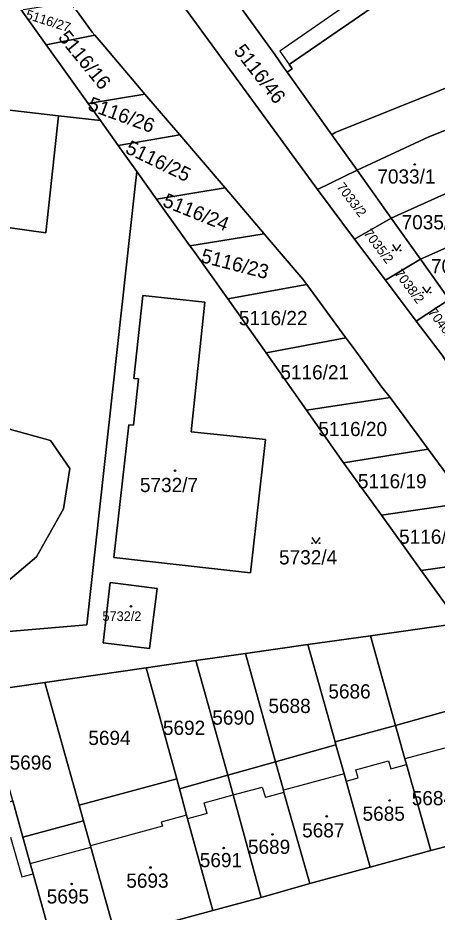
# Model space of a CAD drawing. Extents: x -596233 to -595156, y -1161235 to -1159375.
# Drawn here: x -595296 to -595245.9, y -1160579.1 to -1160472 of the extents above; entities that cross this region are included whole.
import ezdxf

# ---------------------------------------------------------------- set-up
doc = ezdxf.new("R2010")
doc.units = 0
for name, color, linetype in [('KN_CAR_KR', 7, 'Continuous'), ('KN_KULTURY', 7, 'Continuous'), ('KN_PARC_CIS_POZ', 7, 'Continuous'), ('KN_PARC_CIS_STAV', 7, 'Continuous'), ('KN_PARC_PLOCHA', 7, 'Continuous'), ('parcely_l', 7, 'Continuous')]:
    doc.layers.add(name, color=color, linetype=linetype)

msp = doc.modelspace()

# ---------------------------------------------------------------- linework, layer by layer
at = {"layer": 'KN_CAR_KR'}
for points in [[(-595254.62, -1160469.02), (-595264.73, -1160476.04)], [(-595264.73, -1160476.04), (-595263.59, -1160477.64)], [(-595241.88, -1160558.62), (-595249.75, -1160560.73)], [(-595255.63, -1160562.06), (-595251.72, -1160560.99)], [(-595251.72, -1160560.99), (-595251.45, -1160561.96)], [(-595251.45, -1160561.96), (-595249.55, -1160561.44)], [(-595257.03, -1160562.54), (-595264.26, -1160564.51)], [(-595255.36, -1160563.03), (-595255.63, -1160562.06)], [(-595256.79, -1160563.42), (-595255.36, -1160563.03)], [(-595273.78, -1160566.01), (-595270.31, -1160565.07)], [(-595270.31, -1160565.07), (-595266.83, -1160564.14)], [(-595266.83, -1160564.14), (-595266.44, -1160565.39)], [(-595264.23, -1160564.79), (-595266.44, -1160565.39)], [(-595273.42, -1160567.3), (-595273.78, -1160566.01)], [(-595275.86, -1160567.48), (-595278.89, -1160568.31)], [(-595278.89, -1160568.31), (-595278.76, -1160568.8)], [(-595273.42, -1160567.3), (-595275.74, -1160567.93)], [(-595278.76, -1160568.8), (-595287.37, -1160571.16)], [(-595296.91, -1160570.12), (-595295.57, -1160574.88)], [(-595294.57, -1160573.26), (-595287.33, -1160571.32)], [(-595295.57, -1160574.88), (-595294.22, -1160574.5)]]:
    msp.add_lwpolyline(points, dxfattribs=at)
at = {"layer": 'KN_KULTURY'}
for points in [[(-595251.2418, -1160499.1816), (-595250.7418, -1160499.9316), (-595250.2418, -1160499.1816)], [(-595247.6418, -1160504.2316), (-595247.1418, -1160504.9816), (-595246.6418, -1160504.2316)], [(-595260.9018, -1160534.2316), (-595260.4018, -1160534.9816), (-595259.9018, -1160534.2316)]]:
    msp.add_lwpolyline(points, dxfattribs=at)
for centre, radius in [((-595248.58, -1160489.59), 0.09), ((-595248.58, -1160489.59), 0.0398), ((-595251.192, -1160499.8814), 0.05), ((-595250.2926, -1160499.8814), 0.05), ((-595247.592, -1160504.9314), 0.05), ((-595246.6926, -1160504.9314), 0.05), ((-595277.25, -1160526.26), 0.09), ((-595277.25, -1160526.26), 0.0398), ((-595260.852, -1160534.9314), 0.05), ((-595259.9526, -1160534.9314), 0.05), ((-595282.52, -1160542.49), 0.09), ((-595282.52, -1160542.49), 0.0398), ((-595251.59, -1160565.73), 0.09), ((-595251.59, -1160565.73), 0.0398), ((-595259.11, -1160567.64), 0.09), ((-595259.11, -1160567.64), 0.0398), ((-595265.59, -1160569.8), 0.09), ((-595265.59, -1160569.8), 0.0398), ((-595271.44, -1160571.43), 0.09), ((-595271.44, -1160571.43), 0.0398), ((-595280.18, -1160573.76), 0.09), ((-595280.18, -1160573.76), 0.0398), ((-595289.62, -1160575.73), 0.09), ((-595289.62, -1160575.73), 0.0398)]:
    msp.add_circle(centre, radius, dxfattribs=at)
at = {"layer": 'KN_PARC_PLOCHA'}
for points in [[(-595308.89, -1160451.79), (-595304.32, -1160458.48), (-595297.46, -1160468.53), (-595295.64, -1160471.08), (-595292.65, -1160475.27), (-595287.63, -1160482.29), (-595286.17, -1160484.34), (-595291.19, -1160483.77), (-595304.64, -1160482.23), (-595305.5, -1160490.09), (-595324.43, -1160488.01), (-595323.19, -1160476.74), (-595322.1, -1160476.86), (-595320.06, -1160458.35), (-595321.43, -1160458.2), (-595320.75, -1160451.57), (-595313.18, -1160445.5)], [(-595258.48, -1160486.05), (-595263.82, -1160478.56), (-595263.23, -1160478.14), (-595263.59, -1160477.64), (-595250.72, -1160468.73), (-595253.06, -1160460.08), (-595250.26, -1160459.34), (-595248.32, -1160458.82), (-595244.36, -1160457.76), (-595235.34, -1160455.36), (-595231.23, -1160457.04), (-595226.61, -1160473.1), (-595258.08, -1160485.76)], [(-595263.82, -1160478.56), (-595264.19, -1160478.05), (-595265.33, -1160476.45), (-595273.27, -1160465.37), (-595264.02, -1160461.93), (-595260.7, -1160462.12), (-595260.43, -1160462.05), (-595259.54, -1160461.81), (-595253.06, -1160460.08), (-595250.72, -1160468.73), (-595263.59, -1160477.64), (-595263.23, -1160478.14)], [(-595263.82, -1160478.56), (-595258.48, -1160486.05), (-595255.46, -1160490.29), (-595260.2, -1160492.58), (-595277.72, -1160468.56), (-595273.27, -1160465.37), (-595265.33, -1160476.45), (-595264.19, -1160478.05)], [(-595286.85, -1160474.11), (-595292.65, -1160475.27), (-595295.64, -1160471.08), (-595289.76, -1160470.17), (-595287.14, -1160473.77)], [(-595280.85, -1160481.16), (-595287.63, -1160482.29), (-595292.65, -1160475.27), (-595286.85, -1160474.11), (-595286.1, -1160474.99)], [(-595225.34, -1160485.94), (-595227.35, -1160486.69), (-595232.82, -1160488.72), (-595236.44, -1160489.92), (-595242.62, -1160492.06), (-595251.38, -1160496.03), (-595255.46, -1160490.29), (-595246.9, -1160486.28), (-595235.49, -1160481.73), (-595232.66, -1160480.62), (-595232.7, -1160480.51), (-595231.03, -1160479.91), (-595230.9, -1160480.18), (-595230.71, -1160480.59), (-595226.74, -1160479.56), (-595225.77, -1160483.96)], [(-595276.68, -1160486.05), (-595284.04, -1160487.33), (-595286.17, -1160484.34), (-595287.63, -1160482.29), (-595280.85, -1160481.16)], [(-595271.27, -1160492.4), (-595279.45, -1160493.76), (-595281.82, -1160490.44), (-595284.04, -1160487.33), (-595276.68, -1160486.05)], [(-595225.36, -1160492.1), (-595229.56, -1160493.74), (-595229.86, -1160493.85), (-595230.94, -1160494.24), (-595232.66, -1160494.94), (-595232.57, -1160495.27), (-595235.24, -1160496.04), (-595239.01, -1160496.97), (-595247.87, -1160500.92), (-595251.38, -1160496.03), (-595242.62, -1160492.06), (-595236.44, -1160489.92), (-595232.82, -1160488.72), (-595227.35, -1160486.69), (-595226.3, -1160489.49)], [(-595251.38, -1160496.03), (-595255.8, -1160498.52), (-595260.2, -1160492.58), (-595255.46, -1160490.29)], [(-595220.66, -1160496.71), (-595221.93, -1160497.07), (-595223.61, -1160497.57), (-595226.17, -1160498.28), (-595235.6, -1160501.79), (-595244.45, -1160505.74), (-595247.87, -1160500.92), (-595239.01, -1160496.97), (-595235.24, -1160496.04), (-595232.57, -1160495.27), (-595232.66, -1160494.94), (-595230.94, -1160494.24), (-595229.86, -1160493.85), (-595229.56, -1160493.74), (-595225.36, -1160492.1), (-595222.39, -1160491.13), (-595221.32, -1160494.6)], [(-595266.59, -1160497.9), (-595275.47, -1160499.34), (-595279.45, -1160493.76), (-595271.27, -1160492.4)], [(-595247.87, -1160500.92), (-595252.08, -1160503.46), (-595255.8, -1160498.52), (-595251.38, -1160496.03)], [(-595261.48, -1160503.98), (-595270.94, -1160505.68), (-595275.08, -1160499.87), (-595275.47, -1160499.34), (-595266.59, -1160497.9), (-595266.18, -1160498.38), (-595261.96, -1160503.33), (-595261.72, -1160503.65)], [(-595244.45, -1160505.74), (-595248.39, -1160508.35), (-595252.08, -1160503.46), (-595247.87, -1160500.92)], [(-595256.8, -1160510.33), (-595266.33, -1160512.13), (-595270.94, -1160505.68), (-595261.48, -1160503.98)], [(-595273.67, -1160506.09), (-595281.09, -1160505.28), (-595282.18, -1160515.2), (-595281.6, -1160515.27), (-595282.21, -1160520.79), (-595282.78, -1160520.75), (-595284.55, -1160536.66), (-595268.22, -1160538.47), (-595266.42, -1160522.51), (-595275.33, -1160521.59)], [(-595273.67, -1160506.09), (-595275.33, -1160521.59), (-595266.42, -1160522.51), (-595268.22, -1160538.47), (-595284.55, -1160536.66), (-595282.78, -1160520.75), (-595282.21, -1160520.79), (-595281.6, -1160515.27), (-595282.18, -1160515.2), (-595281.09, -1160505.28)], [(-595240.89, -1160510.74), (-595244.72, -1160513.3), (-595245.3, -1160512.43), (-595248.39, -1160508.35), (-595244.45, -1160505.74)], [(-595251.52, -1160517.51), (-595261.51, -1160519.01), (-595266.33, -1160512.13), (-595256.8, -1160510.33), (-595255.81, -1160511.68), (-595252.5, -1160516.26)], [(-595246.97, -1160523.68), (-595257.08, -1160525.32), (-595261.51, -1160519.01), (-595251.52, -1160517.51), (-595247.73, -1160522.65)], [(-595242.27, -1160530.06), (-595252.56, -1160531.58), (-595257.08, -1160525.32), (-595246.97, -1160523.68)], [(-595237.38, -1160536.7), (-595240.33, -1160537.13), (-595247.8, -1160538.2), (-595252.56, -1160531.58), (-595242.27, -1160530.06)], [(-595238.34, -1160543.78), (-595239.05, -1160543.89), (-595243.23, -1160544.53), (-595247.8, -1160538.2), (-595240.33, -1160537.13), (-595237.49, -1160540.81), (-595239.47, -1160542.33)], [(-595279.39, -1160540.35), (-595285, -1160539.65), (-595285.84, -1160546.86), (-595280.31, -1160547.52)], [(-595279.39, -1160540.35), (-595280.31, -1160547.52), (-595285.84, -1160546.86), (-595285, -1160539.65)], [(-595226.46, -1160564.05), (-595224.65, -1160565.64), (-595225.09, -1160565.97), (-595226.01, -1160566.29), (-595226.94, -1160566.53), (-595238.45, -1160569.56), (-595240.18, -1160563.01), (-595235.4, -1160561.69), (-595236.45, -1160555.93), (-595237.5, -1160554.93), (-595242.44, -1160556.5), (-595242.96, -1160554.54), (-595250.87, -1160556.75), (-595253.88, -1160546.01), (-595244, -1160544.61), (-595243.23, -1160544.53), (-595239.39, -1160552.68)], [(-595250.87, -1160556.75), (-595258.09, -1160558.73), (-595261.35, -1160547.07), (-595253.88, -1160546.01)], [(-595258.09, -1160558.73), (-595258, -1160559.07), (-595265.24, -1160561.12), (-595268.82, -1160548.13), (-595261.35, -1160547.07)], [(-595270.94, -1160562.72), (-595276.72, -1160564.35), (-595277.05, -1160563.14), (-595280.7, -1160549.84), (-595274.76, -1160548.99)], [(-595265.24, -1160561.12), (-595270.94, -1160562.72), (-595274.76, -1160548.99), (-595268.82, -1160548.13)], [(-595277.05, -1160563.14), (-595288.73, -1160566.29), (-595292.83, -1160551.59), (-595280.7, -1160549.84)], [(-595288.73, -1160566.29), (-595288.21, -1160568.16), (-595295.44, -1160570.13), (-595296.66, -1160565.79), (-595300.31, -1160552.7), (-595292.83, -1160551.59)], [(-595242.44, -1160556.5), (-595238.96, -1160555.58), (-595237.4, -1160561.47), (-595240.38, -1160562.26), (-595240.18, -1160563.01), (-595238.45, -1160569.56), (-595246.67, -1160571.73), (-595249.55, -1160561.44), (-595249.75, -1160560.73), (-595250.87, -1160556.75), (-595242.96, -1160554.54)], [(-595246.67, -1160571.73), (-595253.91, -1160573.72), (-595256.79, -1160563.42), (-595257.03, -1160562.54), (-595258, -1160559.07), (-595258.09, -1160558.73), (-595250.87, -1160556.75), (-595249.75, -1160560.73), (-595249.55, -1160561.44)], [(-595253.91, -1160573.72), (-595261.14, -1160575.69), (-595264.23, -1160564.79), (-595264.26, -1160564.51), (-595265.24, -1160561.12), (-595258, -1160559.07), (-595257.03, -1160562.54), (-595256.79, -1160563.42)], [(-595261.14, -1160575.69), (-595266.94, -1160577.34), (-595270.31, -1160565.07), (-595270.94, -1160562.72), (-595265.24, -1160561.12), (-595264.26, -1160564.51), (-595264.23, -1160564.79)], [(-595266.94, -1160577.34), (-595272.73, -1160578.9), (-595275.74, -1160567.93), (-595275.86, -1160567.48), (-595276.72, -1160564.35), (-595270.94, -1160562.72), (-595270.31, -1160565.07)], [(-595276.72, -1160564.35), (-595275.86, -1160567.48), (-595275.74, -1160567.93), (-595272.73, -1160578.9), (-595284.33, -1160582.06), (-595287.33, -1160571.32), (-595287.37, -1160571.16), (-595288.21, -1160568.16), (-595288.73, -1160566.29), (-595277.05, -1160563.14)], [(-595295.44, -1160570.13), (-595294.57, -1160573.26), (-595294.22, -1160574.5), (-595291.57, -1160584), (-595301.22, -1160586.59), (-595305.18, -1160572.43), (-595306.31, -1160568.38), (-595296.66, -1160565.79)], [(-595284.33, -1160582.06), (-595291.57, -1160584), (-595294.22, -1160574.5), (-595294.57, -1160573.26), (-595295.44, -1160570.13), (-595288.21, -1160568.16), (-595287.37, -1160571.16), (-595287.33, -1160571.32)]]:
    msp.add_lwpolyline(points, close=True, dxfattribs=at)
for points in [[(-595197.4, -1160471.83), (-595200.29, -1160472.61), (-595206.13, -1160474.14), (-595217.29, -1160477.09), (-595226.74, -1160479.56), (-595230.71, -1160480.59), (-595230.9, -1160480.18), (-595231.03, -1160479.91), (-595232.7, -1160480.51), (-595232.66, -1160480.62), (-595235.49, -1160481.73), (-595246.9, -1160486.28), (-595255.46, -1160490.29), (-595258.48, -1160486.05), (-595258.08, -1160485.76), (-595226.61, -1160473.1), (-595231.23, -1160457.04)], [(-595277.72, -1160468.56), (-595260.2, -1160492.58), (-595255.8, -1160498.52), (-595252.08, -1160503.46), (-595248.39, -1160508.35), (-595245.3, -1160512.43), (-595244.72, -1160513.3), (-595241.31, -1160518.38), (-595237.85, -1160523.27), (-595234.41, -1160528.2), (-595231.19, -1160533.21), (-595227.4, -1160538.06), (-595222.03, -1160544.31), (-595219.31, -1160547.57), (-595216.74, -1160550.64), (-595211.95, -1160556.26), (-595207.69, -1160561.33), (-595207.42, -1160561.24), (-595198.91, -1160571.29), (-595198.25, -1160572.11), (-595185.68, -1160587.63)], [(-595242.27, -1160530.06), (-595246.97, -1160523.68), (-595247.73, -1160522.65), (-595251.52, -1160517.51), (-595252.5, -1160516.26), (-595255.81, -1160511.68), (-595256.8, -1160510.33), (-595261.48, -1160503.98), (-595261.72, -1160503.65), (-595261.96, -1160503.33), (-595266.18, -1160498.38), (-595266.59, -1160497.9), (-595271.27, -1160492.4), (-595276.68, -1160486.05), (-595280.85, -1160481.16), (-595286.1, -1160474.99), (-595286.85, -1160474.11), (-595287.14, -1160473.77), (-595289.76, -1160470.17)], [(-595304.64, -1160482.23), (-595291.19, -1160483.77), (-595292.7, -1160497.77), (-595297.26, -1160497.15)], [(-595297.26, -1160497.15), (-595292.7, -1160497.77), (-595291.19, -1160483.77), (-595286.17, -1160484.34), (-595284.04, -1160487.33), (-595281.82, -1160490.44), (-595282.05, -1160492.54), (-595287.78, -1160544.72), (-595308.87, -1160546.49)], [(-595308.87, -1160546.49), (-595287.78, -1160544.72), (-595282.05, -1160492.54), (-595281.82, -1160490.44), (-595279.45, -1160493.76), (-595275.47, -1160499.34), (-595275.08, -1160499.87), (-595270.94, -1160505.68), (-595266.33, -1160512.13), (-595261.51, -1160519.01), (-595257.08, -1160525.32), (-595252.56, -1160531.58), (-595247.8, -1160538.2), (-595243.23, -1160544.53), (-595244, -1160544.61), (-595253.88, -1160546.01), (-595261.35, -1160547.07), (-595268.82, -1160548.13), (-595274.76, -1160548.99), (-595280.7, -1160549.84), (-595292.83, -1160551.59), (-595300.31, -1160552.7)], [(-595297.74, -1160539.86), (-595293.82, -1160536.57), (-595290.57, -1160530.81), (-595289.85, -1160526), (-595292.16, -1160522.62), (-595297.05, -1160521.27)], [(-595297.05, -1160521.27), (-595292.16, -1160522.62), (-595289.85, -1160526), (-595290.57, -1160530.81), (-595293.82, -1160536.57), (-595297.74, -1160539.86)], [(-595284.33, -1160582.06), (-595272.73, -1160578.9), (-595266.94, -1160577.34), (-595261.14, -1160575.69), (-595253.91, -1160573.72), (-595246.67, -1160571.73), (-595238.45, -1160569.56), (-595226.94, -1160566.53), (-595226.01, -1160566.29), (-595225.09, -1160565.97), (-595224.65, -1160565.64), (-595213.77, -1160575.21), (-595228.87, -1160579.33)]]:
    msp.add_lwpolyline(points, dxfattribs=at)
at = {"layer": 'parcely_l'}
for points in [[(-595235.34, -1160455.36), (-595231.23, -1160457.04), (-595226.61, -1160473.1), (-595258.08, -1160485.76), (-595258.48, -1160486.05)], [(-595291.19, -1160483.77), (-595304.64, -1160482.23), (-595305.5, -1160490.09), (-595324.43, -1160488.01), (-595323.19, -1160476.74), (-595322.1, -1160476.86), (-595320.06, -1160458.35), (-595321.43, -1160458.2)], [(-595263.82, -1160478.56), (-595263.23, -1160478.14), (-595263.59, -1160477.64), (-595250.72, -1160468.73), (-595253.06, -1160460.08)], [(-595273.27, -1160465.37), (-595265.33, -1160476.45), (-595264.19, -1160478.05), (-595263.82, -1160478.56)], [(-595260.2, -1160492.58), (-595277.72, -1160468.56)], [(-595286.85, -1160474.11), (-595287.14, -1160473.77), (-595289.76, -1160470.17)], [(-595295.64, -1160471.08), (-595292.65, -1160475.27)], [(-595286.85, -1160474.11), (-595292.65, -1160475.27)], [(-595280.85, -1160481.16), (-595286.1, -1160474.99), (-595286.85, -1160474.11)], [(-595292.65, -1160475.27), (-595287.63, -1160482.29)], [(-595263.82, -1160478.56), (-595258.48, -1160486.05)], [(-595226.74, -1160479.56), (-595230.71, -1160480.59), (-595230.9, -1160480.18), (-595231.03, -1160479.91), (-595232.7, -1160480.51), (-595232.66, -1160480.62), (-595235.49, -1160481.73), (-595246.9, -1160486.28), (-595255.46, -1160490.29)], [(-595287.63, -1160482.29), (-595280.85, -1160481.16)], [(-595276.68, -1160486.05), (-595280.85, -1160481.16)], [(-595287.63, -1160482.29), (-595286.17, -1160484.34)], [(-595297.05, -1160521.27), (-595298.59, -1160521.09), (-595298.4, -1160519.29), (-595301.91, -1160518.88), (-595301.68, -1160516.33), (-595299.54, -1160516.55), (-595299.35, -1160515.58), (-595297.26, -1160497.15), (-595292.7, -1160497.77), (-595291.19, -1160483.77)], [(-595286.17, -1160484.34), (-595291.19, -1160483.77)], [(-595284.04, -1160487.33), (-595286.17, -1160484.34)], [(-595284.04, -1160487.33), (-595276.68, -1160486.05)], [(-595276.68, -1160486.05), (-595271.27, -1160492.4)], [(-595258.48, -1160486.05), (-595255.46, -1160490.29)], [(-595227.35, -1160486.69), (-595232.82, -1160488.72), (-595236.44, -1160489.92), (-595242.62, -1160492.06), (-595251.38, -1160496.03)], [(-595281.82, -1160490.44), (-595284.04, -1160487.33)], [(-595281.82, -1160490.44), (-595282.05, -1160492.54), (-595287.78, -1160544.72), (-595308.87, -1160546.49), (-595311.78, -1160547.36), (-595315.31, -1160549.11), (-595318.87, -1160552.73), (-595319.87, -1160555.6)], [(-595279.45, -1160493.76), (-595281.82, -1160490.44)], [(-595255.46, -1160490.29), (-595260.2, -1160492.58)], [(-595255.46, -1160490.29), (-595251.38, -1160496.03)], [(-595247.87, -1160500.92), (-595239.01, -1160496.97), (-595235.24, -1160496.04), (-595232.57, -1160495.27), (-595232.66, -1160494.94), (-595230.94, -1160494.24), (-595229.86, -1160493.85), (-595229.56, -1160493.74), (-595225.36, -1160492.1)], [(-595271.27, -1160492.4), (-595279.45, -1160493.76)], [(-595266.59, -1160497.9), (-595271.27, -1160492.4)], [(-595255.8, -1160498.52), (-595260.2, -1160492.58)], [(-595275.47, -1160499.34), (-595279.45, -1160493.76)], [(-595251.38, -1160496.03), (-595255.8, -1160498.52)], [(-595251.38, -1160496.03), (-595247.87, -1160500.92)], [(-595275.47, -1160499.34), (-595266.59, -1160497.9)], [(-595261.48, -1160503.98), (-595261.72, -1160503.65), (-595261.96, -1160503.33), (-595266.18, -1160498.38), (-595266.59, -1160497.9)], [(-595255.8, -1160498.52), (-595252.08, -1160503.46)], [(-595270.94, -1160505.68), (-595275.08, -1160499.87), (-595275.47, -1160499.34)], [(-595252.08, -1160503.46), (-595247.87, -1160500.92)], [(-595247.87, -1160500.92), (-595244.45, -1160505.74)], [(-595270.94, -1160505.68), (-595261.48, -1160503.98)], [(-595261.48, -1160503.98), (-595256.8, -1160510.33)], [(-595248.39, -1160508.35), (-595252.08, -1160503.46)], [(-595273.67, -1160506.09), (-595275.33, -1160521.59), (-595266.42, -1160522.51), (-595268.22, -1160538.47), (-595284.55, -1160536.66), (-595282.78, -1160520.75), (-595282.21, -1160520.79), (-595281.6, -1160515.27), (-595282.18, -1160515.2), (-595281.09, -1160505.28), (-595273.67, -1160506.09)], [(-595266.33, -1160512.13), (-595270.94, -1160505.68)], [(-595244.45, -1160505.74), (-595248.39, -1160508.35)], [(-595248.39, -1160508.35), (-595245.3, -1160512.43), (-595244.72, -1160513.3)], [(-595256.8, -1160510.33), (-595266.33, -1160512.13)], [(-595256.8, -1160510.33), (-595255.81, -1160511.68), (-595252.5, -1160516.26), (-595251.52, -1160517.51)], [(-595261.51, -1160519.01), (-595266.33, -1160512.13)], [(-595251.52, -1160517.51), (-595261.51, -1160519.01)], [(-595246.97, -1160523.68), (-595247.73, -1160522.65), (-595251.52, -1160517.51)], [(-595257.08, -1160525.32), (-595261.51, -1160519.01)], [(-595297.05, -1160521.27), (-595292.16, -1160522.62), (-595289.85, -1160526), (-595290.57, -1160530.81), (-595293.82, -1160536.57), (-595297.74, -1160539.86), (-595301.47, -1160541.23), (-595305.5, -1160541.68), (-595317.68, -1160540.01), (-595321.57, -1160539.46), (-595329.52, -1160538.33), (-595330.79, -1160540.68), (-595332.77, -1160541.55), (-595334.27, -1160541.13), (-595333.94, -1160536.61), (-595334.83, -1160536.51)], [(-595257.08, -1160525.32), (-595246.97, -1160523.68)], [(-595242.27, -1160530.06), (-595246.97, -1160523.68)], [(-595252.56, -1160531.58), (-595257.08, -1160525.32)], [(-595252.56, -1160531.58), (-595242.27, -1160530.06)], [(-595247.8, -1160538.2), (-595252.56, -1160531.58)], [(-595240.33, -1160537.13), (-595247.8, -1160538.2)], [(-595243.23, -1160544.53), (-595247.8, -1160538.2)], [(-595279.39, -1160540.35), (-595280.31, -1160547.52), (-595285.84, -1160546.86), (-595285, -1160539.65), (-595279.39, -1160540.35)], [(-595253.88, -1160546.01), (-595244, -1160544.61), (-595243.23, -1160544.53)], [(-595253.88, -1160546.01), (-595261.35, -1160547.07)], [(-595250.87, -1160556.75), (-595253.88, -1160546.01)], [(-595268.82, -1160548.13), (-595261.35, -1160547.07)], [(-595261.35, -1160547.07), (-595258.09, -1160558.73)], [(-595280.7, -1160549.84), (-595274.76, -1160548.99)], [(-595274.76, -1160548.99), (-595268.82, -1160548.13)], [(-595274.76, -1160548.99), (-595270.94, -1160562.72)], [(-595268.82, -1160548.13), (-595265.24, -1160561.12)], [(-595292.83, -1160551.59), (-595280.7, -1160549.84)], [(-595277.05, -1160563.14), (-595280.7, -1160549.84)], [(-595300.31, -1160552.7), (-595292.83, -1160551.59)], [(-595292.83, -1160551.59), (-595288.73, -1160566.29)], [(-595242.44, -1160556.5), (-595242.96, -1160554.54), (-595250.87, -1160556.75)], [(-595258.09, -1160558.73), (-595250.87, -1160556.75)], [(-595246.67, -1160571.73), (-595249.55, -1160561.44), (-595249.75, -1160560.73), (-595250.87, -1160556.75)], [(-595258, -1160559.07), (-595265.24, -1160561.12)], [(-595258, -1160559.07), (-595258.09, -1160558.73)], [(-595253.91, -1160573.72), (-595256.79, -1160563.42), (-595257.03, -1160562.54), (-595258, -1160559.07)], [(-595265.24, -1160561.12), (-595270.94, -1160562.72)], [(-595261.14, -1160575.69), (-595264.23, -1160564.79), (-595264.26, -1160564.51), (-595265.24, -1160561.12)], [(-595276.72, -1160564.35), (-595270.94, -1160562.72)], [(-595270.94, -1160562.72), (-595270.31, -1160565.07), (-595266.94, -1160577.34)], [(-595288.73, -1160566.29), (-595277.05, -1160563.14)], [(-595276.72, -1160564.35), (-595277.05, -1160563.14)], [(-595272.73, -1160578.9), (-595275.74, -1160567.93), (-595275.86, -1160567.48), (-595276.72, -1160564.35)], [(-595295.44, -1160570.13), (-595296.66, -1160565.79)], [(-595288.73, -1160566.29), (-595288.21, -1160568.16)], [(-595288.21, -1160568.16), (-595295.44, -1160570.13)], [(-595284.33, -1160582.06), (-595287.33, -1160571.32), (-595287.37, -1160571.16), (-595288.21, -1160568.16)], [(-595295.44, -1160570.13), (-595294.57, -1160573.26), (-595294.22, -1160574.5), (-595291.57, -1160584)], [(-595238.45, -1160569.56), (-595246.67, -1160571.73)], [(-595246.67, -1160571.73), (-595253.91, -1160573.72)], [(-595261.14, -1160575.69), (-595253.91, -1160573.72)], [(-595266.94, -1160577.34), (-595261.14, -1160575.69)], [(-595266.94, -1160577.34), (-595272.73, -1160578.9)], [(-595272.73, -1160578.9), (-595284.33, -1160582.06)]]:
    msp.add_lwpolyline(points, dxfattribs=at)

# ---------------------------------------------------------------- texts
at = {"layer": 'KN_PARC_CIS_POZ'}
for s, height, rotation, p in [('5116/27', 1.14, 342.448774, (-595295.2031, -1160472.1141)), ('5116/16', 1.7, 309.318811, (-595291.3106, -1160474.4261)), ('5116/46', 1.7, 308.073287, (-595270.3044, -1160476.0191)), ('5116/26', 1.7, 340.018539, (-595287.7955, -1160483.0336)), ('5116/25', 1.7, 334.300586, (-595283.3061, -1160488.1627)), ('7033/2', 1.14, 307.2693, (-595257.9859, -1160492.2896)), ('5116/24', 1.7, 338.013335, (-595278.8445, -1160494.5485)), ('7035/2', 1.14, 307.243157, (-595254.7548, -1160497.8587)), ('5116/23', 1.7, 345.563453, (-595274.2577, -1160501.2773)), ('7038/2', 1.14, 307.176146, (-595251.0718, -1160502.6564)), ('7040/2', 1.14, 306.896033, (-595247.0492, -1160507.2969))]:
    msp.add_text(s, height=height, rotation=rotation, dxfattribs=at).set_placement(p)
for s, p in [('5116/22', (-595269.6166, -1160508.83)), ('5116/21', (-595264.6466, -1160515.32)), ('5116/20', (-595260.1066, -1160522.11)), ('5116/19', (-595255.3766, -1160528.36)), ('5116/18', (-595250.4466, -1160535)), ('5732/4', (-595264.8066, -1160537.47)), ('5686', (-595258.9066, -1160553.52)), ('5688', (-595266.0766, -1160555.26)), ('5690', (-595272.7966, -1160556.66)), ('5692', (-595278.6966, -1160557.88)), ('5694', (-595287.6166, -1160559.09)), ('5696', (-595297.0366, -1160562.04))]:
    msp.add_text(s, height=1.7, dxfattribs=at).set_placement(p)
at = {"layer": 'KN_PARC_CIS_STAV'}
for s, height, p in [('7033/1', 1.7, (-595253.0466, -1160491.88)), ('7035/1', 1.7, (-595250.1466, -1160497.36)), ('7038/1', 1.7, (-595246.6366, -1160502.62)), ('5732/7', 1.7, (-595281.4466, -1160528.81)), ('5732/2', 1.14, (-595285.93, -1160544.24)), ('5684/2', 1.7, (-595248.9366, -1160566.3)), ('5685', 1.7, (-595254.8166, -1160568.16)), ('5687', 1.7, (-595262.0466, -1160570.15)), ('5689', 1.7, (-595268.5266, -1160572.13)), ('5691', 1.7, (-595274.2866, -1160573.72)), ('5693', 1.7, (-595283.0766, -1160576.18)), ('5695', 1.7, (-595292.5966, -1160578.07))]:
    msp.add_text(s, height=height, dxfattribs=at).set_placement(p)

doc.saveas('drawing.dxf')
